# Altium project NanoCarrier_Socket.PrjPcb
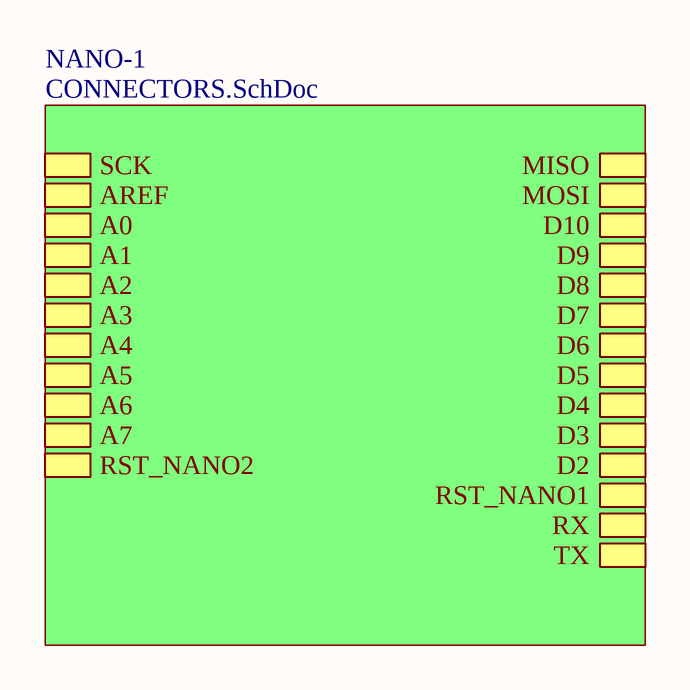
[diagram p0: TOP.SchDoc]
2 sheets, 2 parts. Net scope: hierarchical (ports join the sheet entries above them; power ports are global).
Board files: Nano_Carrier.PcbDoc, Nano Carrier_Panel.PcbDoc
Sheets:
  TOP.SchDoc
    NANO-1 = CONNECTORS.SchDoc

## Sheet TOP.SchDoc
size A3

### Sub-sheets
NANO-1 = CONNECTORS.SchDoc: A6, A5, A1, A4, A7, A3, A0, AREF, SCK, A2, RST_NANO2, RST_NANO1, D2, MOSI, TX, RX, D4, D3, D10, D8, D5, D9, D7, D6, MISO

## Sheet CONNECTORS.SchDoc
size A3; SheetNumber: 2; SheetTotal: 2
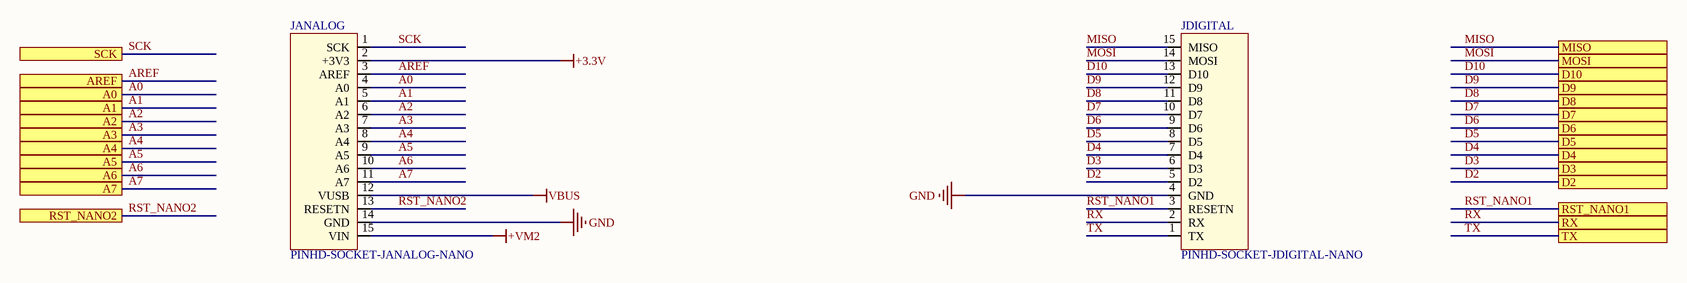
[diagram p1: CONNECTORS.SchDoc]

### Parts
JANALOG  PINHD-SOCKET-JANALOG-NANO  [New footprint 1]
JDIGITAL  PINHD-SOCKET-JDIGITAL-NANO  [New footprint 1]

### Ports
A0, A1, A2, A3, A4, A5, A6, A7, AREF, D2, D3, D4, D5, D6, D7, D8, D9, D10, MISO, MOSI, RST_NANO1, RST_NANO2, RX, SCK, TX

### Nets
+3.3V: JANALOG.2(+3V3)
+VM2: JANALOG.15(VIN)
GND: JANALOG.14(GND) JDIGITAL.4(GND)
VBUS: JANALOG.12(VUSB)
A0: JANALOG.4(A0) ; port A0
A1: JANALOG.5(A1) ; port A1
A2: JANALOG.6(A2) ; port A2
A3: JANALOG.7(A3) ; port A3
A4: JANALOG.8(A4) ; port A4
A5: JANALOG.9(A5) ; port A5
A6: JANALOG.10(A6) ; port A6
A7: JANALOG.11(A7) ; port A7
AREF: JANALOG.3(AREF) ; port AREF
D2: JDIGITAL.5(D2) ; port D2
D3: JDIGITAL.6(D3) ; port D3
D4: JDIGITAL.7(D4) ; port D4
D5: JDIGITAL.8(D5) ; port D5
D6: JDIGITAL.9(D6) ; port D6
D7: JDIGITAL.10(D7) ; port D7
D8: JDIGITAL.11(D8) ; port D8
D9: JDIGITAL.12(D9) ; port D9
D10: JDIGITAL.13(D10) ; port D10
MISO: JDIGITAL.15(MISO) ; port MISO
MOSI: JDIGITAL.14(MOSI) ; port MOSI
RST_NANO1: JDIGITAL.3(RESETN) ; port RST_NANO1
RST_NANO2: JANALOG.13(RESETN) ; port RST_NANO2
RX: JDIGITAL.2(RX) ; port RX
SCK: JANALOG.1(SCK) ; port SCK
TX: JDIGITAL.1(TX) ; port TX

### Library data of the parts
JANALOG = CMP-003-0042-A.1: CONN THD SOCKET F/1/D 15V JANALOG NANO-TYPE
JDIGITAL = CMP-003-0044-A.1: CONN THD SOCKET F/1/D 15V JDIGITAL NANO-TYPE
